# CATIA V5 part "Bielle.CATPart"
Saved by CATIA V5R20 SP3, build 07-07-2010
Part number: Bielle
Bounding box of the stored display mesh (mm): x -3 to 0, y -1.862 to 9.862, z -1.911 to 1.911
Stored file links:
  C:\Documents and Settings\Propriétaire\Mes documents\IFMA\COURS\PROJ IAO\CATIA\Bielle.CATPart
  C:\Documents and Settings\Propriétaire\Mes documents\IFMA\COURS\PROJ IAO\CATIA\dwalter.CATProduct
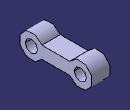
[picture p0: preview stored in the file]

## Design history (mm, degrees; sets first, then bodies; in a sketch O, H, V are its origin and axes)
Set1
  Plane1: linked copy from another document
  Line1: linked copy from another document
  Point1: linked copy from another document
Body1 (main body)
  Sketch1 on Plane1, origin (0, 0, 0), H (0, 1, 0), V (0, 0, 1)
    arc A1 centre (0, 0) radius 2 from (1.7321, 1) to (1.7321, -1) ccw
    arc A2 centre (8, 0) radius 2 from (6.2679, -1) to (6.2679, 1) ccw
    point P1 (8, 0)
    line L1 (6.2679, 1) -> (1.7321, 1)
    point P2 (6.2679, 1)
    point P3 (1.7321, 1)
    line L2 (6.2679, -1) -> (1.7321, -1)
    point P4 (6.2679, -1)
    point P5 (1.7321, -1)
    reference projected line E1 (8, 0) -> (0, 0) from Line1
    reference projected point E2 (8, 0) from Point1
    point P6 (6.2679, 1)
    reference projected line E3 (8, 0) -> (0, 0) from Line1
    reference projected line E4 (8, 0) -> (0, 0) from Line1
    circle A3 centre (8, 0) radius 1
    circle A4 centre (0, 0) radius 1
    construction line L3 (0, 2) -> (8, 2)
    point P7 (0, 2)
    point P8 (8, 2)
    construction line L4 (8, 4) -> (8, -3)
    reference projected point E5 (8, 0) from Point1
    axis line L5 (8, 1) -> (0, 1)
    point P11 (8, 1)
    point P12 (0, 1)
    radius A1 = 2
    radius A4 = 1
    distance L1 L2 = 2
    coincidence: P1 H, P1 E2, P6 P2, P8 A2, P7 A1, P7 V, L4 E5, P8 L4, P12 A4, P11 A3, P11 L4, P12 V
    horizontal: L1 H, L2 H, L3 H, L5 H
    symmetry: L2 L1 E1, P2 P4 E3, P3 P5 E4
    vertical: L4 V
  Pad1: profile Sketch1, direction (-1, 0, 0), length 3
